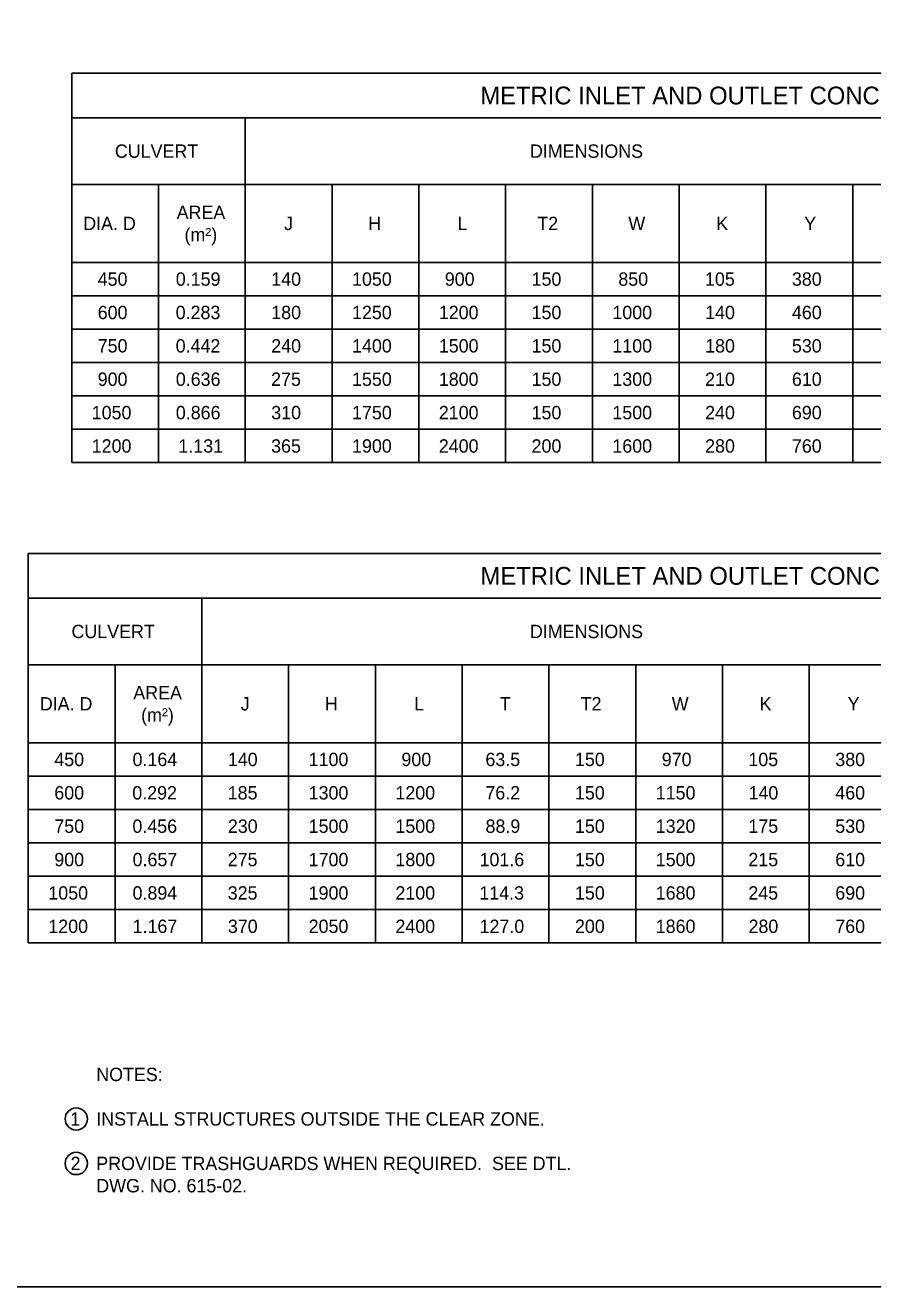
# Model space of a CAD drawing. Extents: x 49991.4 to 50043, y 49987.6 to 50011.4.
# Drawn here: x 50008.63 to 50012.44, y 49987.8 to 49993.47 of the extents above; entities that cross this region are included whole.
import ezdxf

# ---------------------------------------------------------------- set-up
doc = ezdxf.new("R2010")
doc.units = 0
doc.layers.add('Level 1', color=7, linetype='Continuous')
doc.layers.add('Level 2', color=7, linetype='Continuous')

msp = doc.modelspace()

# ---------------------------------------------------------------- linework, layer by layer
at = {"layer": 'Level 1'}
msp.add_lwpolyline([(49999.3835, 49998.9992), (50016.7501, 49998.9992), (50016.7501, 49987.7988), (49999.3835, 49987.7988)], close=True, dxfattribs=at)
at = {"layer": 'Level 2'}
for p, q in [((50008.8375, 49993.2523), (50016.2475, 49993.2523)), ((50008.8375, 49993.0523), (50016.2475, 49993.0523)), ((50008.8375, 49992.7523), (50016.2475, 49992.7523)), ((50008.8375, 49992.4023), (50016.2475, 49992.4023)), ((50008.8375, 49992.2523), (50016.2475, 49992.2523)), ((50008.8375, 49992.1023), (50016.2475, 49992.1023)), ((50008.8375, 49991.9523), (50016.2475, 49991.9523)), ((50008.8375, 49991.8023), (50016.2475, 49991.8023)), ((50008.8375, 49991.6523), (50016.2475, 49991.6523)), ((50008.8375, 49991.5023), (50016.2475, 49991.5023))]:
    msp.add_line(p, q, dxfattribs=at)
for points in [[(50008.8375, 49991.5023), (50008.8375, 49993.2523)], [(50009.6175, 49991.5023), (50009.6175, 49993.0523)], [(50009.2275, 49991.5023), (50009.2275, 49992.7523)], [(50010.0075, 49991.5023), (50010.0075, 49992.7523)], [(50010.3975, 49991.5023), (50010.3975, 49992.7523)], [(50010.7875, 49991.5023), (50010.7875, 49992.7523)], [(50011.1775, 49991.5023), (50011.1775, 49992.7523)], [(50011.5675, 49991.5023), (50011.5675, 49992.7523)], [(50011.9575, 49991.5023), (50011.9575, 49992.7523)], [(50012.3475, 49991.5023), (50012.3475, 49992.7523)], [(50008.6425, 49989.3437), (50008.6425, 49991.0937)], [(50008.6425, 49991.0937), (50016.4425, 49991.0937)], [(50008.6425, 49990.8937), (50016.4425, 49990.8937)], [(50009.4225, 49989.3437), (50009.4225, 49990.8937)], [(50008.6425, 49990.5937), (50016.4425, 49990.5937)], [(50009.0325, 49989.3437), (50009.0325, 49990.5937)], [(50009.8125, 49989.3437), (50009.8125, 49990.5937)], [(50010.2025, 49989.3437), (50010.2025, 49990.5937)], [(50010.5925, 49989.3437), (50010.5925, 49990.5937)], [(50010.9825, 49989.3437), (50010.9825, 49990.5937)], [(50011.3725, 49989.3437), (50011.3725, 49990.5937)], [(50011.7625, 49989.3437), (50011.7625, 49990.5937)], [(50012.1525, 49989.3437), (50012.1525, 49990.5937)], [(50008.6425, 49990.2437), (50016.4425, 49990.2437)], [(50008.6425, 49990.0937), (50016.4425, 49990.0937)], [(50008.6425, 49989.9437), (50016.4425, 49989.9437)], [(50008.6425, 49989.7937), (50016.4425, 49989.7937)], [(50008.6425, 49989.6437), (50016.4425, 49989.6437)], [(50008.6425, 49989.4937), (50016.4425, 49989.4937)], [(50008.6425, 49989.3437), (50016.4425, 49989.3437)]]:
    msp.add_lwpolyline(points, dxfattribs=at)
for centre in [(50008.8578, 49988.553), (50008.8578, 49988.353)]:
    msp.add_circle(centre, 0.05, dxfattribs=at)

# ---------------------------------------------------------------- texts
for s, height, p in [('METRIC INLET AND OUTLET CONCRETE TRANSITIONS FOR CSP', 0.08, (50010.6738, 49993.1123)), ('CULVERT', 0.06, (50009.0315, 49992.8723)), ('DIMENSIONS', 0.06, (50010.897, 49992.8723)), ('AREA', 0.06, (50009.3092, 49992.5973)), ('DIA. D', 0.06, (50008.8893, 49992.5473)), ('J', 0.06, (50009.7922, 49992.5473)), ('H', 0.06, (50010.1705, 49992.5473)), ('L', 0.06, (50010.5713, 49992.5473)), ('T2', 0.06, (50010.93, 49992.5473)), ('W', 0.06, (50011.3393, 49992.5473)), ('K', 0.06, (50011.7344, 49992.5473)), ('Y', 0.06, (50012.1298, 49992.5473)), ('(m²)', 0.06, (50009.3444, 49992.4973)), ('450', 0.06, (50008.9543, 49992.2973)), ('0.159', 0.06, (50009.3054, 49992.2973)), ('140', 0.06, (50009.7343, 49992.2973)), ('1050', 0.06, (50010.0974, 49992.2973)), ('900', 0.06, (50010.5143, 49992.2973)), ('150', 0.06, (50010.9043, 49992.2973)), ('850', 0.06, (50011.2943, 49992.2973)), ('105', 0.06, (50011.6837, 49992.2973)), ('380', 0.06, (50012.0743, 49992.2973)), ('600', 0.06, (50008.9543, 49992.1473)), ('0.283', 0.06, (50009.3047, 49992.1473)), ('180', 0.06, (50009.7343, 49992.1473)), ('1250', 0.06, (50010.0974, 49992.1473)), ('1200', 0.06, (50010.4874, 49992.1473)), ('150', 0.06, (50010.9043, 49992.1473)), ('1000', 0.06, (50011.2674, 49992.1473)), ('140', 0.06, (50011.6843, 49992.1473)), ('460', 0.06, (50012.0743, 49992.1473)), ('750', 0.06, (50008.9543, 49991.9973)), ('0.442', 0.06, (50009.3047, 49991.9973)), ('240', 0.06, (50009.7343, 49991.9973)), ('1400', 0.06, (50010.0974, 49991.9973)), ('1500', 0.06, (50010.4874, 49991.9973)), ('150', 0.06, (50010.9043, 49991.9973)), ('1100', 0.06, (50011.2674, 49991.9973)), ('180', 0.06, (50011.6843, 49991.9973)), ('530', 0.06, (50012.0743, 49991.9973)), ('900', 0.06, (50008.9543, 49991.8473)), ('0.636', 0.06, (50009.3054, 49991.8473)), ('275', 0.06, (50009.7337, 49991.8473)), ('1550', 0.06, (50010.0974, 49991.8473)), ('1800', 0.06, (50010.4874, 49991.8473)), ('150', 0.06, (50010.9043, 49991.8473)), ('1300', 0.06, (50011.2674, 49991.8473)), ('210', 0.06, (50011.6843, 49991.8473)), ('610', 0.06, (50012.0743, 49991.8473)), ('1050', 0.06, (50008.9274, 49991.6973)), ('0.866', 0.06, (50009.3054, 49991.6973)), ('310', 0.06, (50009.7343, 49991.6973)), ('1750', 0.06, (50010.0974, 49991.6973)), ('2100', 0.06, (50010.4874, 49991.6973)), ('150', 0.06, (50010.9043, 49991.6973)), ('1500', 0.06, (50011.2674, 49991.6973)), ('240', 0.06, (50011.6843, 49991.6973)), ('690', 0.06, (50012.0743, 49991.6973)), ('1200', 0.06, (50008.9274, 49991.5473)), ('1.131', 0.06, (50009.3169, 49991.5473)), ('365', 0.06, (50009.7337, 49991.5473)), ('1900', 0.06, (50010.0974, 49991.5473)), ('2400', 0.06, (50010.4874, 49991.5473)), ('200', 0.06, (50010.9043, 49991.5473)), ('1600', 0.06, (50011.2674, 49991.5473)), ('280', 0.06, (50011.6843, 49991.5473)), ('760', 0.06, (50012.0743, 49991.5473)), ('METRIC INLET AND OUTLET CONCRETE TRANSITIONS FOR RCP', 0.08, (50010.6749, 49990.9537)), ('CULVERT', 0.06, (50008.8365, 49990.7137)), ('DIMENSIONS', 0.06, (50010.897, 49990.7137)), ('AREA', 0.06, (50009.1142, 49990.4387)), ('DIA. D', 0.06, (50008.6943, 49990.3887)), ('J', 0.06, (50009.5972, 49990.3887)), ('H', 0.06, (50009.9755, 49990.3887)), ('L', 0.06, (50010.3763, 49990.3887)), ('T', 0.06, (50010.7615, 49990.3887)), ('T2', 0.06, (50011.125, 49990.3887)), ('W', 0.06, (50011.5343, 49990.3887)), ('K', 0.06, (50011.9294, 49990.3887)), ('Y', 0.06, (50012.3248, 49990.3887)), ('(m²)', 0.06, (50009.1494, 49990.3387)), ('450', 0.06, (50008.7593, 49990.1387)), ('0.164', 0.06, (50009.1109, 49990.1387)), ('140', 0.06, (50009.5393, 49990.1387)), ('1100', 0.06, (50009.9024, 49990.1387)), ('900', 0.06, (50010.3193, 49990.1387)), ('63.5', 0.06, (50010.6969, 49990.1387)), ('150', 0.06, (50011.0993, 49990.1387)), ('970', 0.06, (50011.4893, 49990.1387)), ('105', 0.06, (50011.8787, 49990.1387)), ('380', 0.06, (50012.2693, 49990.1387)), ('600', 0.06, (50008.7593, 49989.9887)), ('0.292', 0.06, (50009.1097, 49989.9887)), ('185', 0.06, (50009.5387, 49989.9887)), ('1300', 0.06, (50009.9024, 49989.9887)), ('1200', 0.06, (50010.2924, 49989.9887)), ('76.2', 0.06, (50010.6967, 49989.9887)), ('150', 0.06, (50011.0993, 49989.9887)), ('1150', 0.06, (50011.4624, 49989.9887)), ('140', 0.06, (50011.8793, 49989.9887)), ('460', 0.06, (50012.2693, 49989.9887)), ('750', 0.06, (50008.7593, 49989.8387)), ('0.456', 0.06, (50009.1104, 49989.8387)), ('230', 0.06, (50009.5393, 49989.8387)), ('1500', 0.06, (50009.9024, 49989.8387)), ('1500', 0.06, (50010.2924, 49989.8387)), ('88.9', 0.06, (50010.6973, 49989.8387)), ('150', 0.06, (50011.0993, 49989.8387)), ('1320', 0.06, (50011.4624, 49989.8387)), ('175', 0.06, (50011.8787, 49989.8387)), ('530', 0.06, (50012.2693, 49989.8387)), ('900', 0.06, (50008.7593, 49989.6887)), ('0.657', 0.06, (50009.1111, 49989.6887)), ('275', 0.06, (50009.5387, 49989.6887)), ('1700', 0.06, (50009.9024, 49989.6887)), ('1800', 0.06, (50010.2924, 49989.6887)), ('101.6', 0.06, (50010.6704, 49989.6887)), ('150', 0.06, (50011.0993, 49989.6887)), ('1500', 0.06, (50011.4624, 49989.6887)), ('215', 0.06, (50011.8787, 49989.6887)), ('610', 0.06, (50012.2693, 49989.6887)), ('1050', 0.06, (50008.7324, 49989.5387)), ('0.894', 0.06, (50009.1109, 49989.5387)), ('325', 0.06, (50009.5387, 49989.5387)), ('1900', 0.06, (50009.9024, 49989.5387)), ('2100', 0.06, (50010.2924, 49989.5387)), ('114.3', 0.06, (50010.6697, 49989.5387)), ('150', 0.06, (50011.0993, 49989.5387)), ('1680', 0.06, (50011.4624, 49989.5387)), ('245', 0.06, (50011.8787, 49989.5387)), ('690', 0.06, (50012.2693, 49989.5387)), ('1200', 0.06, (50008.7324, 49989.3887)), ('1.167', 0.06, (50009.1111, 49989.3887)), ('370', 0.06, (50009.5393, 49989.3887)), ('2050', 0.06, (50009.9024, 49989.3887)), ('2400', 0.06, (50010.2924, 49989.3887)), ('127.0', 0.06, (50010.6705, 49989.3887)), ('200', 0.06, (50011.0993, 49989.3887)), ('1860', 0.06, (50011.4624, 49989.3887)), ('280', 0.06, (50011.8793, 49989.3887)), ('760', 0.06, (50012.2693, 49989.3887)), ('NOTES:', 0.06, (50008.9478, 49988.723)), ('1', 0.06, (50008.8309, 49988.523)), ('INSTALL STRUCTURES OUTSIDE THE CLEAR ZONE.', 0.06, (50008.9478, 49988.523)), ('2', 0.06, (50008.8327, 49988.323)), ('PROVIDE TRASHGUARDS WHEN REQUIRED.  SEE DTL.', 0.06, (50008.9478, 49988.323)), ('DWG. NO. 615-02.', 0.06, (50008.9478, 49988.223))]:
    msp.add_text(s, height=height, dxfattribs=at).set_placement(p)

doc.saveas('drawing.dxf')
